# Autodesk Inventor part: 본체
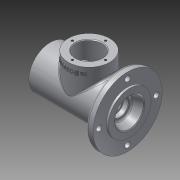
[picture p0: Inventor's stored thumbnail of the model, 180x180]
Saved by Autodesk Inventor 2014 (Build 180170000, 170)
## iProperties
Created: 2016-08
Part Number: 본체
Material: Aluminum 6061
Document SubType Name: Modeling
Designer: user
Density: 2.71 g/cm^3
Appearance: Aluminum - Flat
Mass: 735.004 g
Surface Area: 618.326 cm^2
Volume: 271.219 cm^3
Author: user
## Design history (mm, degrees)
sketch "Sketch1"
  geometry: C1 r 50 at (0, 0); 1 further point
  constraints: 1 centre point, 1 coincident
  dimensions: "d0" = 100 diameter of C1
extrude "Extrusion1" new body sketch "Sketch1" distance "d1" = 13; taper "d2" = 0 deg
sketch "Sketch2"
  geometry: C1 r 50 at (0, 0) reference; C2 r 31 at (0, 0)
  constraints: 1 centre point, 1 coincident
  dimensions: "d3" = 62 diameter of C2
extrude "Extrusion2" join sketch "Sketch2" distance "d4" = 102; taper "d5" = 0 deg
sketch "Sketch3"
  geometry: C1 r 50 at (0, 0) reference; C2 r 31 at (0, 0)
  constraints: 1 centre point, 1 coincident
  dimensions: "d6" = 62 diameter of C2
extrude "Extrusion3" cut sketch "Sketch3" distance "d7" = 3; taper "d8" = 0 deg
sketch "Sketch4"
  geometry: L1 (0, 31)-(0, -31) reference; L2 (106, 0)-(0, 0); L3 (0, 0)-(0, 21); L4 (0, 21)-(14, 16); L5 (14, 16)-(14, 12.904); L6 (21.3, 12.5)-(21.3, 10); L7 (21.3, 10)-(24, 10); L8 (24, 10)-(24, 16.5); L9 (24, 16.5)-(29, 16.5); L10 (78, 26)-(78, 17.5); L11 (78, 17.5)-(89, 17.5); L12 (89, 17.5)-(89, 18.5); L13 (89, 18.5)-(90.75, 18.5); L14 (90.75, 18.5)-(90.75, 17.5); L15 (90.75, 17.5)-(94, 17.5); L16 (94, 17.5)-(94, 20); L17 (94, 20)-(103, 20); L18 (103, 20)-(103, 24); L19 (103, 24)-(106, 24); L20 (106, 24)-(106, 0); L21 (14, 12.904)-(14.7, 12.5); L22 (14.7, 12.5)-(21.3, 12.5); L23 (29, 16.5)-(29, 17.5); L24 (29, 17.5)-(40, 17.5); L25 (40, 17.5)-(40, 26); L26 (40, 26)-(78, 26); L27 (115, -31)-(115, 31) reference
  constraints: 50 end point, 7 perpendicular, 5 parallel, 5 vertical alignment, 2 horizontal alignment, 1 point on line
  dimensions: "d9" = 32 diameter of L4.end L2; "d10" = 42 diameter of L3.end L2; "d11" = 14 horizontal distance of L3.end L4.end; "d13" = 0.7 horizontal distance of L5.end L21.end; "d14" = 30 deg angle of L22 L21; "d15" = 7.3 distance between parallel lines of L5 L6; "d16" = 2.7 distance of L6.end L7.end; "d17" = 25 diameter of L22 L2; "d18" = 20 diameter of L7 L2; "d19" = 33 diameter of L9 L2; "d20" = 35 diameter of L24 L2; "d21" = 5 distance of L8.end L9.end; "d22" = 11 distance of L23.end L24.end; "d23" = 38 distance of L25.end L10.start; "d24" = 52 diameter of L26 L2; "d25" = 35 diameter of L11 L2; "d26" = 11 distance of L10.end L11.end; "d27" = 1.75 distance of L12.end L13.end; "d28" = 37 diameter of L13 L2; "d29" = 5 horizontal distance of L12.end L15.end; "d30" = 9 distance of L16.end L17.end; "d31" = 3 distance of L18.end L19.end; "d32" = 40 diameter of L17 L2; "d33" = 48 diameter of L19 L2
revolve "Revolution1" sketch "Sketch4" stored, may be unused: angle "d35" = 90 deg
hole "Hole1" diameter "d38" = 40.376; stored, may be unused: countersink angle "d42" = 90 deg, drill point angle "d44" = 0 deg; dims "d36" = 10, "d37" = 10, "d39" = 6, "d40" = 4, "d41" = 2, "d43" = 9
chamfer "Chamfer1" distance "d45" = 1; stored, may be unused: second distance "d46" = 2, angle "d47" = 45 deg
fillet "Fillet1" dims "d48" = 0.3
fillet "Fillet2" dims "d49" = 0.3
fillet "Fillet3" dims "d50" = 3
chamfer "Chamfer2" distance "d51" = 1; stored, may be unused: second distance "d52" = 2, angle "d53" = 45 deg
fillet "Fillet4" dims "d54" = 3
workplane "Work Plane1"
sketch "Sketch5"
  geometry: L1 (-115, 31)-(-115, -31) reference; C1 r 30 at (-59, 0); 1 further point
  constraints: 1 centre point, 1 horizontal alignment
  dimensions: "d56" = 60 diameter of C1; "d57" = 56 distance from line of L1 C1.centre
extrude "Extrusion4" join sketch "Sketch5" stored distance "d58" = 10; taper "d59" = 0 deg
hole "Hole2" diameter "d62" = 38; stored, may be unused: countersink angle "d66" = 90 deg, drill point angle "d68" = 0 deg; dims "d60" = 10, "d61" = 10, "d63" = 6, "d64" = 4, "d65" = 2, "d67" = 8
sketch "Sketch7"
  geometry: C1 r 31 at (0, 0) reference; C2 r 50 at (0, 0) reference; C3 r 4 at (-41.5, 0); C4 r 4 at (0, 41.5); C5 r 4 at (41.5, 0); C6 r 4 at (0, -41.5); A1 r 41.5 centre (0, 0) between (-41.5, 0) and (0, 41.5)
  constraints: 5 centre point, 4 point on circle, 2 horizontal alignment, 2 vertical alignment, 1 coincident
  dimensions: "d81" = 83 diameter of A1; "d82" = 8 diameter of C3; "d83" = 8 diameter of C4; "d84" = 8 diameter of C5; "d85" = 8 diameter of C6
extrude "Extrusion5" cut sketch "Sketch7" distance "d86" = 10; taper "d87" = 0 deg
workplane "Work Plane2"
sketch "Sketch8"
  geometry: L1 (-89, 50)-(-29, 50) reference; L2 (-115, 31)-(-115, -31) reference; 2 further points
  constraints: 1 other
  dimensions: "d89" = 10 distance from line of L1 point (-59, 40); "d90" = 56 distance from line of L2 point (-59, 40)
emboss "Emboss1" sketch "Sketch8" dims "d2" = 0, "d9" = 32, "d10" = 42, "d11" = 14, "d13" = 0.7, "d14" = 30 deg, "d15" = 7.3, "d16" = 2.7, "d17" = 25, "d18" = 20, "d19" = 33, "d20" = 35, "d21" = 5, "d22" = 11, "d23" = 38, "d24" = 52, "d25" = 35, "d26" = 11, "d27" = 1.75, "d28" = 37, "d29" = 5, "d30" = 9, "d31" = 3, "d32" = 40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
fillet "Fillet5" dims "d93" = 3
chamfer "Chamfer3" distance "d94" = 1; stored, may be unused: second distance "d95" = 2, angle "d96" = 45 deg
workplane "Work Plane3"
sketch "Sketch9"
  geometry: C1 r 30 at (-59, 0) reference; 1 further point
extrude "Extrusion6" cut sketch "Sketch9" distance "d98" = 1; taper "d99" = 0 deg
sketch "Sketch10"
  geometry: C1 r 19 at (0, 0) reference; C2 r 30 at (0, 0) reference; C3 r 2 at (0, 24); C4 r 2 at (24, 0); C5 r 2 at (0, -24); C6 r 2 at (-24, 0); A1 r 24 centre (0, 0) between (0, 24) and (24, 0); 1 further point
  constraints: 5 centre point, 4 point on circle, 2 horizontal alignment, 2 vertical alignment, 1 coincident
  dimensions: "d100" = 48 diameter of A1; "d101" = 4 diameter of C3; "d102" = 4 diameter of C4; "d103" = 4 diameter of C5; "d104" = 4 diameter of C6
hole "Hole4" sketch "Sketch10" at (0, 24), (24, 0), (0, -24), (-24, 0) diameter "d105" = 3.242; stored, may be unused: countersink angle "d109" = 90 deg, drill point angle "d111" = 118 deg; dims "d106" = 8, "d107" = 4, "d108" = 2, "d110" = 10
chamfer "Chamfer4" distance "d112" = 1; stored, may be unused: second distance "d113" = 2, angle "d114" = 45 deg
body "Solid1"
other parameters: "d88" = -61.75, "d97" = 49
